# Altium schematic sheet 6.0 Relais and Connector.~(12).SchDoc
size A4; SheetNumber: 6; SheetTotal: 7
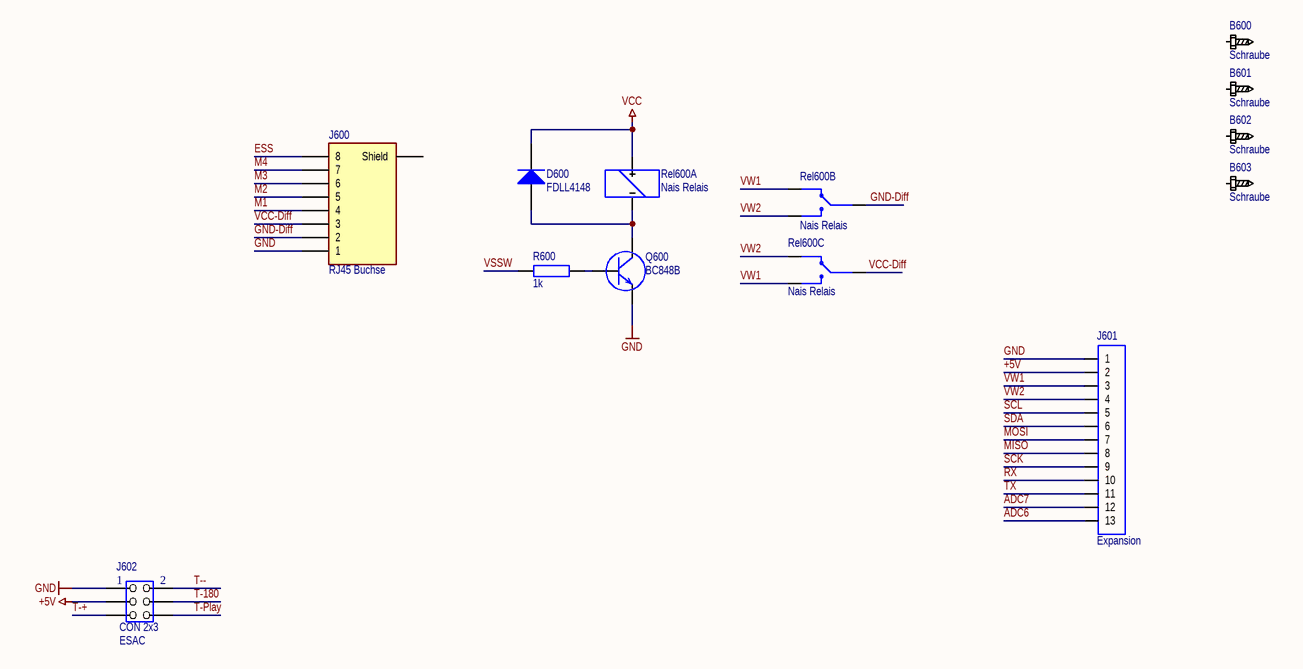
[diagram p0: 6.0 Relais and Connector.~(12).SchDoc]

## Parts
B600  Schraube  [B_Schraube-M3]
B601  Schraube  [B_Schraube-M3]
B602  Schraube  [B_Schraube-M3]
B603  Schraube  [B_Schraube-M3]
D600  FDLL4148  [D_SMD_1206]
J600  RJ45 Buchse  [J_TE-RJ45-8L-B]
J601  Expansion  [SIP-13]
J602  CON 2x3  Use: ESAC  [J_2x3]
Q600  BC848B  [SOT-23]
R600  1k  [R_SMD_0805]
Rel600  Nais Relais  [Rel_THT_Nais]  (parts A,B,C of 3)

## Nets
+5V: J601.2 J602.3
GND: J600.1 J601.1 J602.1 Q600.2(E)
VCC: D600.2(K) Rel600.5
ADC6: J601.13
ADC7: J601.12
ESS: J600.8
GND-Diff: J600.2 Rel600.3
M1: J600.4
M2: J600.5
M3: J600.6
M4: J600.7
MISO: J601.8
MOSI: J601.7
RX: J601.10
SCK: J601.9
SCL: J601.5
SDA: J601.6
T-180: J602.4
T-+: J602.5
T--: J602.2
T-Play: J602.6
TX: J601.11
VCC-Diff: J600.3 Rel600.6
VSSW: R600.1
VW1: J601.3 Rel600.2 Rel600.8
VW2: J601.4 Rel600.1 Rel600.7
NetD600_1: D600.1(A) Q600.3(C) Rel600.4
NetQ600_1: Q600.1(B) R600.2

Not connected (* = marked no-connect by the designer): B600 1(PAD); B601 1(PAD); B602 1(PAD); B603 1(PAD); J600 MP(Shield)

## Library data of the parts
B600-B603 = B_Schraube: Schraubenloch für M3 Schrauben
D600 = D_SMD_Silizium: Diode SMD Silizium; Spannung For.: 0,7V
J600 = J_RJ45: Connector
J601 = J_THT_CON13: Stecker
J602 = J_THT_IDC 2x3: Stecker
Q600 = Q_SMD_NPN: NPN Transistor
R600 = R_SMD_Widerstand: Widerstand SMD
Rel600 = Rel_THT_Nais: Nais DS2Y-S-DC12V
